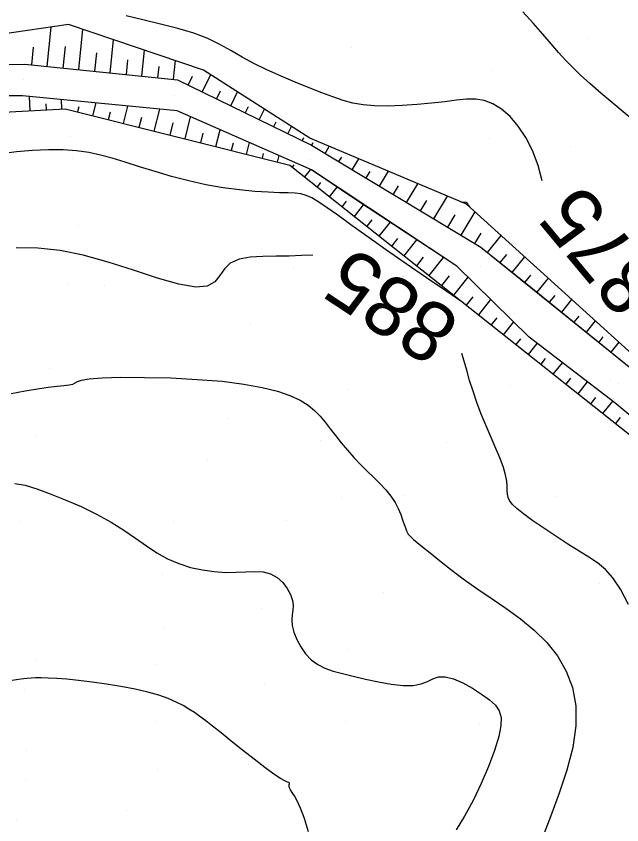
# Model space of a CAD drawing. Extents: x 400243 to 403697, y 4403637 to 4408083.
# Drawn here: x 402783.5 to 402859.8, y 4405990.3 to 4406092.2 of the extents above; entities that cross this region are included whole.
import ezdxf

# ---------------------------------------------------------------- set-up
doc = ezdxf.new("R2010")
doc.units = 0
doc.layers.add('HH_DiS', color=7, linetype='Continuous')
doc.layers.add('HH_IC', color=7, linetype='Continuous')

msp = doc.modelspace()

# ---------------------------------------------------------------- linework, layer by layer
at = {"layer": 'HH_DiS'}
msp.add_line((402818.02, 4406073.42), (402818.02, 4406073.42), dxfattribs=at)
at = {"layer": 'HH_IC'}
for p, q in [((402790.08, 4406091.13), (402781.43, 4406089.87)), ((402787.38, 4406085.86), (402787.89, 4406090.81)), ((402790.08, 4406091.13), (402790.08, 4406091.13)), ((402807.1, 4406085.38), (402790.08, 4406091.13)), ((402791.36, 4406085.45), (402791.88, 4406090.53)), ((402795.34, 4406085.04), (402795.76, 4406089.21)), ((402855.64, 4406089.38), (402855.64, 4406089.38)), ((402785.62, 4406088.29), (402785.39, 4406086.06)), ((402789.65, 4406088.38), (402789.37, 4406085.65)), ((402793.58, 4406087.56), (402793.35, 4406085.25)), ((402799.32, 4406084.63), (402799.65, 4406087.9)), ((402825.78, 4406088.23), (402825.78, 4406088.23)), ((402788.73, 4406086.63), (402788.73, 4406086.63)), ((402797.52, 4406086.7), (402797.33, 4406084.84)), ((402803.29, 4406084.23), (402803.54, 4406086.58)), ((402765.3, 4406085.84), (402784.58, 4406086.15)), ((402765.3, 4406085.84), (402784.58, 4406086.15)), ((402784.58, 4406086.15), (402803.81, 4406084.17)), ((402784.58, 4406086.15), (402803.81, 4406084.17)), ((402784.58, 4406086.15), (402784.58, 4406086.15)), ((402801.45, 4406085.84), (402801.3, 4406084.43)), ((402807.1, 4406085.38), (402807.1, 4406085.38)), ((402820.49, 4406076.82), (402807.1, 4406085.38)), ((402805.67, 4406084.6), (402805.14, 4406083.52)), ((402806.94, 4406082.64), (402808, 4406084.81)), ((402843.5, 4406085.33), (402843.5, 4406085.33)), ((402784.38, 4406084.25), (402784.38, 4406084.25)), ((402803.81, 4406084.17), (402820.7, 4406075.91)), ((402803.81, 4406084.17), (402820.7, 4406075.91)), ((402803.81, 4406084.17), (402803.81, 4406084.17)), ((402806.44, 4406083.37), (402806.44, 4406083.37)), ((402809.21, 4406082.74), (402808.73, 4406081.76)), ((402810.53, 4406080.88), (402811.39, 4406082.64)), ((402784.29, 4406082.15), (402765.11, 4406082.15)), ((402784.29, 4406082.15), (402765.11, 4406082.15)), ((402784.29, 4406082.15), (402765.11, 4406082.15)), ((402784.29, 4406082.15), (402784.29, 4406082.15)), ((402803.77, 4406080.25), (402784.29, 4406082.15)), ((402803.77, 4406080.25), (402784.29, 4406082.15)), ((402803.77, 4406080.25), (402784.29, 4406082.15)), ((402785.25, 4406080.27), (402785.15, 4406082.06)), ((402789.24, 4406080.48), (402789.18, 4406081.67)), ((402790.09, 4406081.93), (402790.09, 4406081.93)), ((402803.39, 4406082.24), (402803.39, 4406082.24)), ((402719.34, 4406076.76), (402789.63, 4406080.5)), ((402719.34, 4406076.76), (402789.63, 4406080.5)), ((402787.2, 4406081.12), (402787.24, 4406080.37)), ((402789.63, 4406080.5), (402789.63, 4406080.5)), ((402789.63, 4406080.5), (402817.97, 4406073.41)), ((402789.63, 4406080.5), (402817.97, 4406073.41)), ((402791.36, 4406080.78), (402791.19, 4406080.11)), ((402793.13, 4406079.63), (402793.54, 4406081.25)), ((402797.01, 4406078.65), (402797.56, 4406080.85)), ((402800.89, 4406077.68), (402801.59, 4406080.46)), ((402812.71, 4406080.78), (402812.33, 4406080.01)), ((402814.12, 4406079.13), (402814.78, 4406080.47)), ((402795.31, 4406080.1), (402795.07, 4406079.14)), ((402799.26, 4406079.41), (402798.95, 4406078.17)), ((402803.77, 4406080.25), (402803.77, 4406080.25)), ((402820.72, 4406072.81), (402803.77, 4406080.25)), ((402820.72, 4406072.81), (402803.77, 4406080.25)), ((402820.72, 4406072.81), (402803.77, 4406080.25)), ((402804.77, 4406076.71), (402805.47, 4406079.5)), ((402803.22, 4406078.73), (402802.83, 4406077.2)), ((402816.2, 4406078.82), (402815.92, 4406078.25)), ((402817.72, 4406077.37), (402818.17, 4406078.3)), ((402807.02, 4406077.46), (402806.71, 4406076.23)), ((402808.65, 4406075.74), (402809.19, 4406077.88)), ((402790.27, 4406077.02), (402790.27, 4406077.02)), ((402812.53, 4406074.77), (402812.9, 4406076.25)), ((402819.69, 4406076.85), (402819.51, 4406076.49)), ((402820.49, 4406076.82), (402820.49, 4406076.82)), ((402840.26, 4406068.47), (402820.49, 4406076.82)), ((402820.89, 4406076.24), (402820.7, 4406075.91)), ((402843.11, 4406076.73), (402843.11, 4406076.73)), ((402810.82, 4406076.16), (402810.59, 4406075.25)), ((402820.7, 4406075.91), (402842.05, 4406063.07)), ((402820.7, 4406075.91), (402842.05, 4406063.07)), ((402820.7, 4406075.91), (402820.7, 4406075.91)), ((402822.41, 4406074.88), (402822.95, 4406075.78)), ((402853.35, 4406075.7), (402853.35, 4406075.7)), ((402790.6, 4406074.28), (402790.6, 4406074.28)), ((402814.62, 4406074.86), (402814.47, 4406074.28)), ((402816.41, 4406073.8), (402816.62, 4406074.62)), ((402824.47, 4406074.42), (402824.12, 4406073.85)), ((402825.84, 4406072.82), (402826.67, 4406074.21)), ((402817.97, 4406073.41), (402872.49, 4406030.16)), ((402817.97, 4406073.41), (402817.97, 4406073.41)), ((402818.49, 4406073.43), (402818.28, 4406073.16)), ((402820.55, 4406074.11), (402820.55, 4406074.11)), ((402829.11, 4406073.97), (402829.11, 4406073.97)), ((402819.85, 4406071.92), (402820.6, 4406072.87)), ((402826.24, 4406069.06), (402820.72, 4406072.81)), ((402826.24, 4406069.06), (402820.72, 4406072.81)), ((402820.72, 4406072.81), (402820.72, 4406072.81)), ((402839.04, 4406060.66), (402820.72, 4406072.81)), ((402828.04, 4406072.61), (402827.55, 4406071.79)), ((402828.22, 4406072.48), (402828.22, 4406072.48)), ((402829.27, 4406070.76), (402830.4, 4406072.64)), ((402821.84, 4406071.22), (402821.41, 4406070.68)), ((402822.98, 4406069.43), (402823.93, 4406070.63)), ((402831.62, 4406070.79), (402830.98, 4406069.73)), ((402832.69, 4406068.7), (402834.12, 4406071.06)), ((402836.12, 4406066.64), (402837.84, 4406069.49)), ((402825.07, 4406068.85), (402824.55, 4406068.19)), ((402825.74, 4406068.1), (402825.74, 4406068.1)), ((402826.11, 4406066.95), (402827.26, 4406068.39)), ((402826.24, 4406069.06), (402826.24, 4406069.06)), ((402839.04, 4406060.66), (402826.24, 4406069.06)), ((402839.04, 4406060.66), (402826.24, 4406069.06)), ((402835.19, 4406068.97), (402834.41, 4406067.67)), ((402840.26, 4406068.47), (402840.26, 4406068.47)), ((402861.99, 4406048.8), (402840.26, 4406068.47)), ((402838.77, 4406067.16), (402837.84, 4406065.61)), ((402839.55, 4406064.57), (402841.32, 4406067.51)), ((402828.31, 4406066.5), (402827.68, 4406065.71)), ((402829.25, 4406064.46), (402830.62, 4406066.19)), ((402791.31, 4406065.83), (402791.31, 4406065.83)), ((402831.56, 4406064.15), (402830.82, 4406063.22)), ((402832.38, 4406061.98), (402833.98, 4406063.99)), ((402842.05, 4406064.85), (402841.27, 4406063.54)), ((402842.89, 4406062.39), (402844.62, 4406064.53)), ((402851.13, 4406064.41), (402851.13, 4406064.41)), ((402839.94, 4406063.38), (402839.94, 4406063.38)), ((402842.05, 4406063.07), (402860.76, 4406047.99)), ((402842.05, 4406063.07), (402847.94, 4406058.37)), ((402842.05, 4406063.07), (402842.05, 4406063.07)), ((402845.28, 4406062.16), (402844.45, 4406061.14)), ((402834.8, 4406061.81), (402833.95, 4406060.73)), ((402835.52, 4406059.49), (402837.34, 4406061.78)), ((402846.01, 4406059.88), (402847.59, 4406061.84)), ((402818.46, 4406060.33), (402818.46, 4406060.33)), ((402839.04, 4406060.66), (402839.04, 4406060.66)), ((402848.13, 4406051.73), (402839.04, 4406060.66)), ((402848.13, 4406051.73), (402839.04, 4406060.66)), ((402848.13, 4406051.73), (402839.04, 4406060.66)), ((402842.06, 4406060.59), (402842.06, 4406060.59)), ((402832.16, 4406059.41), (402832.16, 4406059.41)), ((402838.05, 4406059.47), (402837.08, 4406058.25)), ((402838.65, 4406057.01), (402840.45, 4406059.28)), ((402848.32, 4406059.56), (402847.56, 4406058.63)), ((402849.12, 4406057.37), (402850.56, 4406059.15)), ((402789.96, 4406058.34), (402789.96, 4406058.34)), ((402794.6, 4406058.18), (402794.6, 4406058.18)), ((402847.94, 4406058.37), (402847.94, 4406058.37)), ((402847.94, 4406058.37), (402860.76, 4406047.99)), ((402851.36, 4406056.96), (402850.68, 4406056.12)), ((402841.05, 4406056.82), (402840.22, 4406055.76)), ((402841.78, 4406054.52), (402843.32, 4406056.46)), ((402852.24, 4406054.86), (402853.53, 4406056.46)), ((402829.37, 4406055.74), (402829.37, 4406055.74)), ((402844.05, 4406054.16), (402843.35, 4406053.28)), ((402846.31, 4406054.66), (402846.31, 4406054.66)), ((402854.4, 4406054.36), (402853.79, 4406053.6)), ((402855.35, 4406052.35), (402856.5, 4406053.77)), ((402813.05, 4406053.41), (402813.05, 4406053.41)), ((402844.92, 4406052.03), (402846.19, 4406053.64)), ((402857.44, 4406051.76), (402856.91, 4406051.09)), ((402847.05, 4406051.51), (402846.48, 4406050.79)), ((402848.05, 4406049.55), (402849.16, 4406050.94)), ((402848.13, 4406051.73), (402848.13, 4406051.73)), ((402858.96, 4406043.44), (402848.13, 4406051.73)), ((402858.96, 4406043.44), (402848.13, 4406051.73)), ((402858.96, 4406043.44), (402848.13, 4406051.73)), ((402858.46, 4406049.84), (402859.47, 4406051.08)), ((402847.96, 4406049.85), (402847.96, 4406049.85)), ((402850.18, 4406049.02), (402849.62, 4406048.31)), ((402787.68, 4406047.74), (402787.68, 4406047.74)), ((402851.18, 4406047.06), (402852.34, 4406048.51)), ((402853.34, 4406046.56), (402852.75, 4406045.82)), ((402854.32, 4406044.58), (402855.51, 4406046.08)), ((402858.36, 4406046.44), (402858.36, 4406046.44)), ((402859.43, 4406045.94), (402859.43, 4406045.94)), ((402825.39, 4406045.18), (402825.39, 4406045.18)), ((402845.85, 4406045.58), (402845.85, 4406045.58)), ((402856.49, 4406044.1), (402855.89, 4406043.33)), ((402857.45, 4406042.09), (402858.69, 4406043.65)), ((402874.12, 4406030.79), (402858.96, 4406043.44)), ((402874.12, 4406030.79), (402858.96, 4406043.44)), ((402858.96, 4406043.44), (402858.96, 4406043.44)), ((402874.12, 4406030.79), (402858.96, 4406043.44)), ((402859.63, 4406041.61), (402859.02, 4406040.85)), ((402810.21, 4406041.44), (402810.21, 4406041.44)), ((402785.91, 4406039.26), (402785.91, 4406039.26)), ((402821.88, 4406038.74), (402821.88, 4406038.74)), ((402837.67, 4406038.41), (402837.67, 4406038.41)), ((402807.59, 4406036.13), (402807.59, 4406036.13)), ((402824.47, 4406031.47), (402824.47, 4406031.47)), ((402832.35, 4406031.82), (402832.35, 4406031.82)), ((402851.4, 4406031.69), (402851.4, 4406031.69)), ((402784.03, 4406028.51), (402784.03, 4406028.51)), ((402803.36, 4406028.45), (402803.36, 4406028.45)), ((402817.57, 4406028.63), (402817.57, 4406028.63)), ((402832.56, 4406026.53), (402832.56, 4406026.53)), ((402801.87, 4406021.75), (402801.87, 4406021.75)), ((402857.07, 4406020.69), (402857.07, 4406020.69)), ((402829.79, 4406019.54), (402829.79, 4406019.54)), ((402814.42, 4406017.47), (402814.42, 4406017.47)), ((402802, 4406015.07), (402802, 4406015.07)), ((402825.21, 4406012.33), (402825.21, 4406012.33)), ((402786.09, 4406010.92), (402786.09, 4406010.92)), ((402801.15, 4406010.41), (402801.15, 4406010.41)), ((402814.83, 4406007.97), (402814.83, 4406007.97)), ((402784.54, 4406007.29), (402784.54, 4406007.29)), ((402801.08, 4406003.3), (402801.08, 4406003.3)), ((402825.05, 4406003.3), (402825.05, 4406003.3)), ((402841.87, 4406002.92), (402841.87, 4406002.92)), ((402784.74, 4405999.58), (402784.74, 4405999.58)), ((402812.77, 4405997.81), (402812.77, 4405997.81)), ((402801.32, 4405997.22), (402801.32, 4405997.22)), ((402784.68, 4405995.84), (402784.68, 4405995.84)), ((402817.42, 4405994.99), (402817.42, 4405994.99)), ((402818.28, 4405994.13), (402818.28, 4405994.13)), ((402797.33, 4405992.11), (402797.33, 4405992.11)), ((402783.55, 4405990.86), (402783.55, 4405990.86))]:
    msp.add_line(p, q, dxfattribs=at)
for points in [[(402871.88, 4406067.49), (402870, 4406069.91), (402868.34, 4406072), (402867.03, 4406073.61), (402865.97, 4406074.82), (402865.05, 4406075.79), (402864.11, 4406076.66), (402863.03, 4406077.6), (402861.72, 4406078.69), (402860.24, 4406079.92), (402858.69, 4406081.21), (402857.18, 4406082.49), (402855.8, 4406083.68), (402854.63, 4406084.74), (402853.63, 4406085.7), (402852.72, 4406086.63), (402851.84, 4406087.61), (402850.9, 4406088.68), (402849.85, 4406089.91), (402848.67, 4406091.27), (402847.34, 4406092.72)], [(402849.79, 4406071.45), (402849.26, 4406073.38), (402848.58, 4406075.24), (402847.74, 4406076.9), (402846.77, 4406078.34), (402845.73, 4406079.54), (402844.64, 4406080.48), (402843.55, 4406081.15), (402842.48, 4406081.55), (402841.41, 4406081.71), (402840.26, 4406081.71), (402838.98, 4406081.58), (402837.52, 4406081.4), (402835.83, 4406081.21), (402834.01, 4406081.04), (402832.14, 4406080.92), (402830.32, 4406080.85), (402828.65, 4406080.88), (402827.2, 4406081), (402825.91, 4406081.23), (402824.68, 4406081.57), (402823.41, 4406082), (402822.01, 4406082.53), (402820.41, 4406083.16), (402818.66, 4406083.86), (402816.86, 4406084.61), (402815.09, 4406085.41), (402813.43, 4406086.23), (402811.95, 4406087.04), (402810.55, 4406087.85), (402809.15, 4406088.63), (402807.63, 4406089.36), (402805.89, 4406090.04), (402803.86, 4406090.65), (402801.67, 4406091.2), (402799.45, 4406091.72), (402797.36, 4406092.21)], [(402839.8, 4406056.1), (402837.5, 4406057.63), (402835.19, 4406059.21), (402832.63, 4406060.98), (402830.05, 4406062.78), (402827.66, 4406064.46), (402825.65, 4406065.9), (402824.01, 4406067.09), (402822.68, 4406068.03), (402821.62, 4406068.76), (402820.75, 4406069.27), (402820.03, 4406069.6), (402819.36, 4406069.79), (402818.65, 4406069.87), (402817.78, 4406069.9), (402816.68, 4406069.93), (402815.25, 4406069.99), (402813.55, 4406070.1), (402811.63, 4406070.28), (402809.56, 4406070.55), (402807.4, 4406070.93), (402805.22, 4406071.42), (402803.06, 4406071.98), (402800.98, 4406072.59), (402799.01, 4406073.2), (402797.21, 4406073.77), (402795.59, 4406074.27), (402794.09, 4406074.68), (402792.62, 4406075), (402791.09, 4406075.23), (402789.41, 4406075.34), (402787.53, 4406075.35), (402785.53, 4406075.26), (402783.52, 4406075.08), (402781.64, 4406074.83)], [(402840.29, 4406068.67), (402840.23, 4406068.69), (402840.16, 4406068.69), (402840.08, 4406068.69), (402840, 4406068.69), (402839.92, 4406068.68), (402839.84, 4406068.69), (402839.78, 4406068.7), (402839.72, 4406068.71), (402839.68, 4406068.72), (402839.67, 4406068.72)], [(402840.72, 4406068.06), (402840.66, 4406068.15), (402840.61, 4406068.21), (402840.56, 4406068.27), (402840.51, 4406068.33), (402840.48, 4406068.36), (402840.46, 4406068.39), (402840.45, 4406068.41), (402840.44, 4406068.43), (402840.43, 4406068.46), (402840.42, 4406068.5), (402840.4, 4406068.54), (402840.38, 4406068.59), (402840.34, 4406068.64), (402840.29, 4406068.67)], [(402820.89, 4406062.07), (402819.44, 4406062.01), (402817.89, 4406061.95), (402816.23, 4406061.93), (402814.56, 4406061.9), (402812.97, 4406061.8), (402811.57, 4406061.54), (402810.47, 4406061.07), (402809.72, 4406060.34), (402809.14, 4406059.5), (402808.5, 4406058.71), (402807.57, 4406058.16), (402806.11, 4406058.02), (402803.98, 4406058.4), (402801.29, 4406059.18), (402798.26, 4406060.17), (402795.07, 4406061.2), (402791.94, 4406062.07), (402789.01, 4406062.64), (402786.22, 4406062.93), (402783.47, 4406062.98)], [(402860.65, 4406018.04), (402859.64, 4406019.95), (402858.69, 4406021.4), (402857.75, 4406022.46), (402856.77, 4406023.29), (402855.68, 4406024.01), (402854.45, 4406024.76), (402853.02, 4406025.65), (402851.5, 4406026.63), (402849.99, 4406027.63), (402848.59, 4406028.59), (402847.43, 4406029.44), (402846.58, 4406030.12), (402846.01, 4406030.67), (402845.67, 4406031.12), (402845.49, 4406031.53), (402845.41, 4406031.94), (402845.39, 4406032.4), (402845.37, 4406032.95), (402845.31, 4406033.59), (402845.17, 4406034.37), (402844.9, 4406035.31), (402844.49, 4406036.43), (402843.95, 4406037.7), (402843.35, 4406039.08), (402842.72, 4406040.53), (402842.11, 4406042.01), (402841.56, 4406043.48), (402841.07, 4406044.91), (402840.64, 4406046.28), (402840.27, 4406047.55), (402839.95, 4406048.69), (402839.67, 4406049.68)], [(402782.86, 4406044.61), (402784.59, 4406044.95), (402786.17, 4406045.23), (402787.52, 4406045.42), (402788.63, 4406045.54), (402789.5, 4406045.63), (402790.15, 4406045.71), (402790.6, 4406045.81), (402790.89, 4406045.95), (402791.19, 4406046.13), (402791.72, 4406046.32), (402792.69, 4406046.48), (402794.3, 4406046.61), (402796.68, 4406046.67), (402799.65, 4406046.66), (402802.95, 4406046.58), (402806.31, 4406046.41), (402809.46, 4406046.16), (402812.19, 4406045.82), (402814.49, 4406045.4), (402816.41, 4406044.92), (402817.98, 4406044.37), (402819.26, 4406043.78), (402820.28, 4406043.15), (402821.1, 4406042.48), (402821.8, 4406041.76), (402822.43, 4406041), (402823.05, 4406040.18), (402823.73, 4406039.31), (402824.46, 4406038.4), (402825.24, 4406037.48), (402826.05, 4406036.57), (402826.88, 4406035.68), (402827.73, 4406034.84), (402828.57, 4406034.03), (402829.37, 4406033.25), (402830.09, 4406032.47), (402830.72, 4406031.69), (402831.23, 4406030.9), (402831.64, 4406030.11), (402831.95, 4406029.37), (402832.19, 4406028.7), (402832.39, 4406028.13), (402832.55, 4406027.68), (402832.68, 4406027.33), (402832.8, 4406027.08), (402832.91, 4406026.89), (402833.01, 4406026.75), (402833.13, 4406026.62), (402833.3, 4406026.47), (402833.58, 4406026.23), (402834.03, 4406025.86), (402834.71, 4406025.31), (402835.65, 4406024.53), (402836.84, 4406023.57), (402838.24, 4406022.47), (402839.81, 4406021.28), (402841.53, 4406020.05), (402843.35, 4406018.81), (402845.2, 4406017.55), (402847.04, 4406016.22), (402848.78, 4406014.8), (402850.36, 4406013.25), (402851.72, 4406011.54), (402852.82, 4406009.64), (402853.6, 4406007.55), (402854.02, 4406005.26), (402854.03, 4406002.75), (402853.63, 4406000.01), (402852.89, 4405997.14), (402851.94, 4405994.23), (402850.87, 4405991.37), (402849.82, 4405988.66)], [(402783.32, 4406033.3), (402784.59, 4406033.05), (402786.06, 4406032.6), (402787.77, 4406031.99), (402789.67, 4406031.23), (402791.65, 4406030.36), (402793.6, 4406029.4), (402795.43, 4406028.4), (402797.06, 4406027.38), (402798.52, 4406026.38), (402799.89, 4406025.42), (402801.21, 4406024.55), (402802.57, 4406023.8), (402803.99, 4406023.18), (402805.47, 4406022.71), (402806.97, 4406022.38), (402808.44, 4406022.17), (402809.86, 4406022.08), (402811.19, 4406022.1), (402812.42, 4406022.16), (402813.56, 4406022.2), (402814.59, 4406022.13), (402815.53, 4406021.89), (402816.36, 4406021.43), (402817.08, 4406020.79), (402817.65, 4406020.06), (402818.07, 4406019.29), (402818.32, 4406018.55), (402818.4, 4406017.91), (402818.36, 4406017.32), (402818.27, 4406016.74), (402818.21, 4406016.11), (402818.26, 4406015.39), (402818.47, 4406014.55), (402818.84, 4406013.63), (402819.34, 4406012.7), (402819.96, 4406011.82), (402820.68, 4406011.06), (402821.49, 4406010.46), (402822.4, 4406010), (402823.43, 4406009.64), (402824.62, 4406009.31), (402825.97, 4406008.99), (402827.51, 4406008.63), (402829.14, 4406008.28), (402830.75, 4406007.99), (402832.25, 4406007.82), (402833.54, 4406007.81), (402834.53, 4406008.02), (402835.32, 4406008.33), (402836.01, 4406008.66), (402836.72, 4406008.89), (402837.55, 4406008.91), (402838.59, 4406008.65), (402839.77, 4406008.15), (402840.99, 4406007.48), (402842.14, 4406006.74), (402843.14, 4406006), (402843.89, 4406005.32), (402844.38, 4406004.61), (402844.61, 4406003.78), (402844.58, 4406002.74), (402844.3, 4406001.37), (402843.76, 4405999.63), (402843.01, 4405997.62), (402842.1, 4405995.46), (402841.08, 4405993.32), (402840, 4405991.33), (402838.92, 4405989.61)], [(402820.33, 4405989.36), (402819.81, 4405991.06), (402819.33, 4405992.35), (402818.91, 4405993.27), (402818.54, 4405993.91), (402818.25, 4405994.34), (402818.05, 4405994.66), (402817.94, 4405994.92), (402817.9, 4405995.14), (402817.9, 4405995.32), (402817.91, 4405995.45), (402817.91, 4405995.53), (402817.84, 4405995.57), (402817.67, 4405995.63), (402817.34, 4405995.78), (402816.78, 4405996.1), (402815.95, 4405996.65), (402814.82, 4405997.48), (402813.46, 4405998.52), (402812.01, 4405999.66), (402810.59, 4406000.8), (402809.3, 4406001.84), (402808.24, 4406002.69), (402807.37, 4406003.37), (402806.63, 4406003.93), (402805.95, 4406004.41), (402805.26, 4406004.85), (402804.51, 4406005.29), (402803.65, 4406005.73), (402802.65, 4406006.16), (402801.47, 4406006.58), (402800.08, 4406006.98), (402798.46, 4406007.35), (402796.68, 4406007.69), (402794.84, 4406008), (402793.04, 4406008.25), (402791.35, 4406008.46), (402789.87, 4406008.6), (402788.59, 4406008.7), (402787.51, 4406008.75), (402786.63, 4406008.77), (402785.93, 4406008.77), (402785.38, 4406008.75), (402784.82, 4406008.7), (402784.07, 4406008.6), (402782.96, 4406008.45)]]:
    msp.add_lwpolyline(points, dxfattribs=at)

# ---------------------------------------------------------------- texts
for s, rotation, p in [('875', 129.7442, (402865.43, 4406058.51)), ('885', 146.5921, (402839.78, 4406054.1))]:
    msp.add_text(s, height=7.5, rotation=rotation, dxfattribs=at).set_placement(p)

doc.saveas('drawing.dxf')
